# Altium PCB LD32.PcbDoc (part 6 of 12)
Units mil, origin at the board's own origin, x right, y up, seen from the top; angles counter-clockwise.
Board outline 7007.87 x 4368.85 mil, 12 copper layers (Top Layer, Int1 (GND), Int2 (AVDD), Int3 (DVDD), Int4 (GND), Int5 (ST), Int6 (SB), Int8 (AGND), Int7 (AVCC), Int9 (VCCA), Int10 (GND), Bottom Layer), stack 60.136 mil thick; 1165 components, 667 nets, 3910 pads, 2570 vias.
Unrouted connection lines stored in the file: 14.
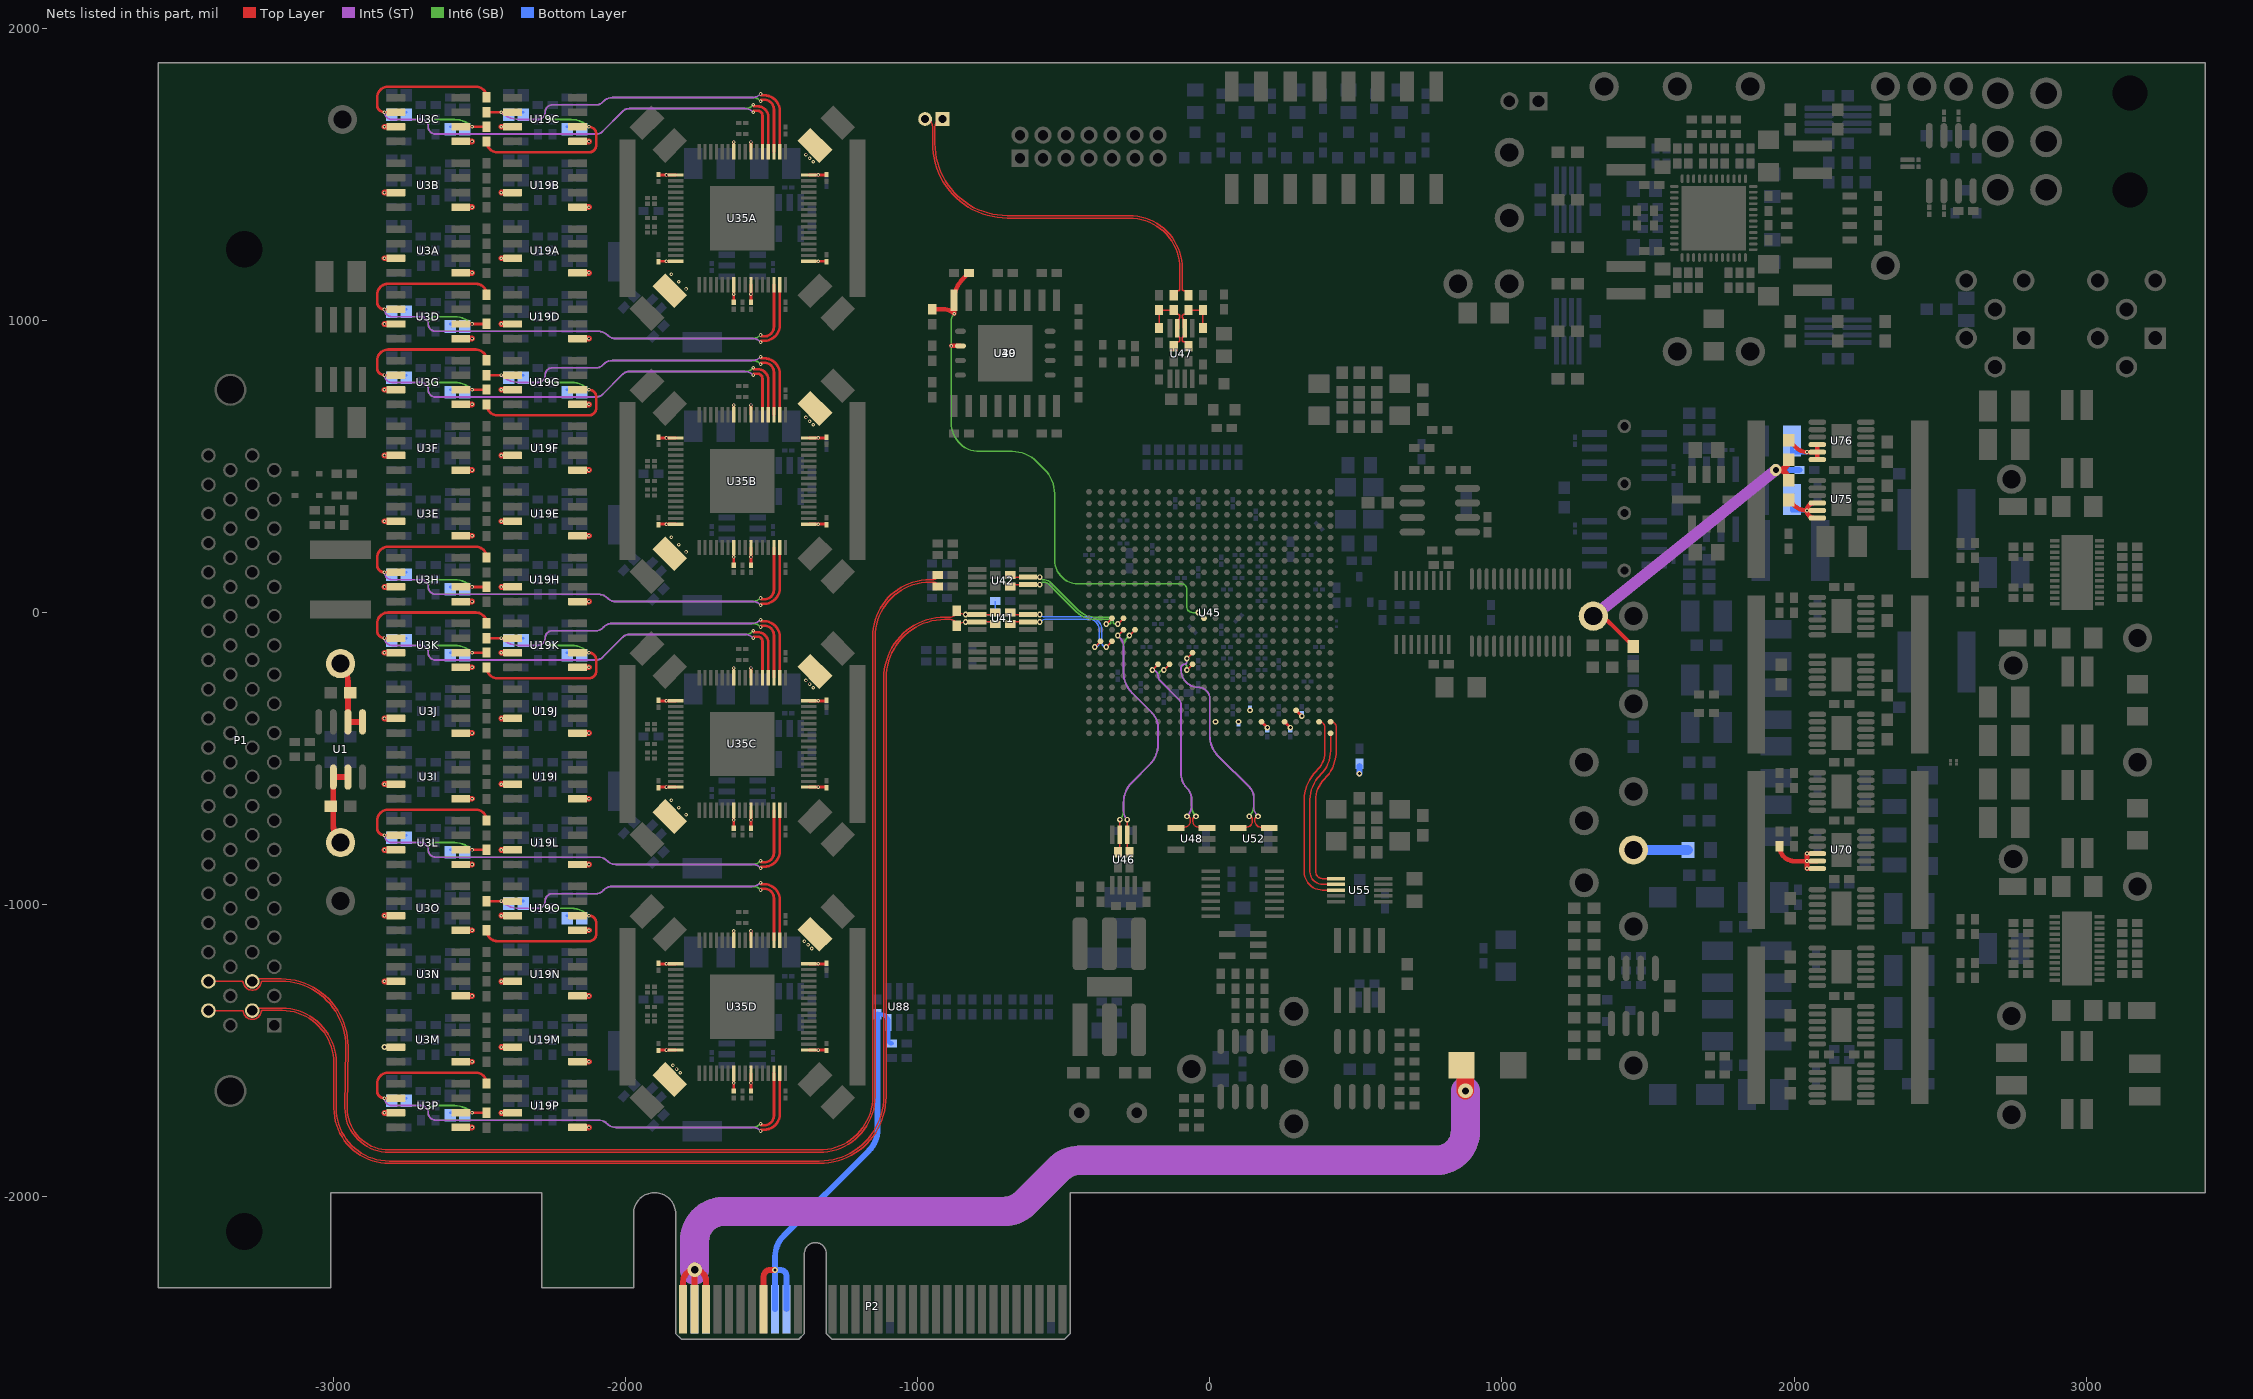
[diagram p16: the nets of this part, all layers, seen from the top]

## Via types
v1: diameter 12, hole 6, Top Layer to Bottom Layer, tented both sides, 1500 vias
v2: diameter 19, hole 10, Top Layer to Bottom Layer, tented both sides, 404 vias
v3: diameter 20, hole 10, Top Layer to Bottom Layer, tented both sides, 337 vias
v4: diameter 14, hole 7, Top Layer to Bottom Layer, tented both sides, 212 vias
v5: diameter 30, hole 15, Top Layer to Bottom Layer, tented both sides, 37 vias
v6: diameter 19.68, hole 7.87, Top Layer to Bottom Layer, 25 vias
v7: diameter 40, hole 20, Top Layer to Bottom Layer, tented both sides, 16 vias
v8: diameter 19.02, hole 10, Top Layer to Bottom Layer, tented both sides, 10 vias
v9: diameter 40, hole 20, Top Layer to Bottom Layer, 9 vias
v10: diameter 60, hole 40, Top Layer to Bottom Layer, 5 vias
v11: diameter 25, hole 13, Top Layer to Bottom Layer, 4 vias
v12: diameter 50, hole 25, Top Layer to Bottom Layer, tented both sides, 4 vias
v13: diameter 35, hole 20, Top Layer to Bottom Layer, 2 vias
v14: diameter 50, hole 25, Top Layer to Bottom Layer, 2 vias
v15: diameter 63, hole 45, Top Layer to Bottom Layer, 1 vias
v16: diameter 14.02, hole 7.01, Top Layer to Bottom Layer, tented both sides, 1 vias
v17: diameter 60, hole 40, Top Layer to Bottom Layer, tented both sides, 1 vias

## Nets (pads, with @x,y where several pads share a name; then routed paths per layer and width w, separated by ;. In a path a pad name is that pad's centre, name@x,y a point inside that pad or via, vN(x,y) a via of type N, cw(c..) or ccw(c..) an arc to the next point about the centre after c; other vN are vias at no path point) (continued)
AVCC3.3V: C7A.2 C7B.2 C7C.2 C7D.2 C19A.2 C19B.2 C19C.2 C19D.2 C20A.2 C20B.2 C20C.2 C20D.2 C27A.2 C27B.2 C27C.2 C27D.2 C31A.2 C31B.2 C31C.2 C31D.2 C44A.2 C44B.2 C44C.2 C44D.2 C51A.2 C51B.2 C51C.2 C51D.2 C52A.2 C52B.2 C52C.2 C52D.2 R138.1 R152.1 R272.1 R273.2 TP15.1 U35A.7 U35A.10 U35A.17 U35A.32 U35A.39 U35A.42 U35A.49 U35A.64 U35B.7 U35B.10 U35B.17 U35B.32 U35B.39 U35B.42 U35B.49 U35B.64 U35C.7 U35C.10 U35C.17 U35C.32 U35C.39 U35C.42 U35C.49 U35C.64 U35D.7 U35D.10 U35D.17 U35D.32 U35D.39 U35D.42 U35D.49 U35D.64 | length 2853.9
  Top Layer w10: C19D.2@-1887.5,-1499.44 cw(c-1885.7,-1499.44) -1885.7,-1497.64 -1869.73,-1497.64 v1(-1860,-1497.64) U35D.32@-1827.5,-1497.64 ; C20D.2@-1887.5,-1200.56 ccw(c-1885.7,-1200.56) -1885.7,-1202.36 -1869.73,-1202.36 v1(-1860,-1202.36) U35D.17@-1827.5,-1202.36 ; C19C.2@-1887.5,-599.44 cw(c-1885.7,-599.44) -1885.7,-597.64 -1869.73,-597.64 v1(-1860,-597.64) U35C.32@-1827.5,-597.64 ; C20C.2@-1887.5,-300.56 ccw(c-1885.7,-300.56) -1885.7,-302.36 -1869.73,-302.36 v1(-1860,-302.36) U35C.17@-1827.5,-302.36 ; C19B.2@-1887.5,300.56 cw(c-1885.7,300.56) -1885.7,302.36 -1869.73,302.36 v1(-1860,302.36) U35B.32@-1827.5,302.36 ; C20B.2@-1887.5,599.44 ccw(c-1885.7,599.44) -1885.7,597.64 -1869.73,597.64 v1(-1860,597.64) U35B.17@-1827.5,597.64 ; C19A.2@-1887.5,1200.56 cw(c-1885.7,1200.56) -1885.7,1202.36 -1869.73,1202.36 v1(-1860,1202.36) U35A.32@-1827.5,1202.36 ; C20A.2@-1887.5,1499.44 ccw(c-1885.7,1499.44) -1885.7,1497.64 -1869.73,1497.64 v1(-1860,1497.64) U35A.17@-1827.5,1497.64 ; C27D.2@-1629.53,-1632.5 v1(-1629.53,-1610) U35D.39@-1629.53,-1577.5 ; U35D.10@-1629.53,-1122.5 v1(-1629.53,-1090) ; C27C.2@-1629.53,-732.5 v1(-1629.53,-710) U35C.39@-1629.53,-677.5 ; U35C.10@-1629.53,-222.5 v1(-1629.53,-190) ; C27B.2@-1629.53,167.5 v1(-1629.53,190) U35B.39@-1629.53,222.5 ; U35B.10@-1629.53,677.5 v1(-1629.53,710) ; C27A.2@-1629.53,1067.5 v1(-1629.53,1090) U35A.39@-1629.53,1122.5 ; U35A.10@-1629.53,1577.5 v1(-1629.53,1610) ; C31D.2@-1570.47,-1632.5 v1(-1570.47,-1610) U35D.42@-1570.47,-1577.5 ; U35D.7@-1570.47,-1122.5 v1(-1570.47,-1090) ; C31C.2@-1570.47,-732.5 v1(-1570.47,-710) U35C.42@-1570.47,-677.5 ; U35C.7@-1570.47,-222.5 v1(-1570.47,-190) ; C31B.2@-1570.47,167.5 v1(-1570.47,190) U35B.42@-1570.47,222.5 ; U35B.7@-1570.47,677.5 v1(-1570.47,710) ; C31A.2@-1570.47,1067.5 v1(-1570.47,1090) U35A.42@-1570.47,1122.5 ; U35A.7@-1570.47,1577.5 v1(-1570.47,1610) ; U35D.49@-1372.5,-1497.64 v1(-1340,-1497.64) -1330.27,-1497.64 -1314.3,-1497.64 cw(c-1314.3,-1499.44) C51D.2@-1312.5,-1499.44 ; U35D.64@-1372.5,-1202.36 v1(-1340,-1202.36) -1330.27,-1202.36 -1314.3,-1202.36 ccw(c-1314.3,-1200.56) C52D.2@-1312.5,-1200.56 ; U35C.49@-1372.5,-597.64 v1(-1340,-597.64) -1330.27,-597.64 -1314.3,-597.64 cw(c-1314.3,-599.44) C51C.2@-1312.5,-599.44 ; U35C.64@-1372.5,-302.36 v1(-1340,-302.36) -1330.27,-302.36 -1314.3,-302.36 ccw(c-1314.3,-300.56) C52C.2@-1312.5,-300.56 ; U35B.49@-1372.5,302.36 v1(-1340,302.36) -1330.27,302.36 -1314.3,302.36 cw(c-1314.3,300.56) C51B.2@-1312.5,300.56 ; U35B.64@-1372.5,597.64 v1(-1340,597.64) -1330.27,597.64 -1314.3,597.64 ccw(c-1314.3,599.44) C52B.2@-1312.5,599.44 ; U35A.49@-1372.5,1202.36 v1(-1340,1202.36) -1330.27,1202.36 -1314.3,1202.36 cw(c-1314.3,1200.56) C51A.2@-1312.5,1200.56 ; U35A.64@-1372.5,1497.64 v1(-1340,1497.64) -1330.27,1497.64 -1314.3,1497.64 ccw(c-1314.3,1499.44) C52A.2@-1312.5,1499.44
  Top Layer w15: TP15.1@1312.5,-12.5 cw(c1312.5,-93.29) 1369.63,-36.16 R138.1@1450,-116.54
  Top Layer w20: v7(1937.5,487.5) v7@1945.96,487.5 ; R273.2@1981.25,452.21 ccw(c1945.96,452.21) v7@1945.96,487.5 ; R272.1@1981.25,522.79 cw(c1945.96,522.79) v7@1945.96,487.5
  Int5 (ST) w40: TP15.1@1312.5,-12.5 v7(1937.5,487.5)
  Bottom Layer w20: v7(1937.5,487.5) R152.1@2018.16,487.5
  other v1: -1812.5,-1575 -1825,-1562.5 -1837.5,-1550 -1362.5,-1150 -1375,-1137.5 -1387.5,-1125 -1792.5,-692.5 -1817.5,-667.5 -1842.5,-642.5 -1357.5,-257.5 -1370,-245 -1382.5,-232.5 -1792.5,207.5 -1817.5,232.5 -1842.5,257.5 -1357.5,642.5 -1370,655 -1382.5,667.5 -1792.5,1107.5 -1817.5,1132.5 -1842.5,1157.5 -1357.5,1542.5 -1370,1555 -1382.5,1567.5
AVCCL3.3V: C170.2 R273.1 U75.10 U75.11 U75.12 | length 290.4
  Top Layer w15: R273.1@1981.25,385.29 1998.8,367.73 ccw(c2043.75,412.68) v4(2043.75,349.11) ; U75.12@2069.34,323.52 cw(c2069.34,349.11) v4(2043.75,349.11) ; U75.11@2079.44,349.11 v4(2043.75,349.11) ; U75.10@2079.44,374.7 2069.34,374.7 ccw(c2069.34,349.11) v4(2043.75,349.11)
  Bottom Layer w15: C170.2@1992.62,387.5 1992.62,349.11 v4(2043.75,349.11)
AVCCR3.3V: C171.2 R272.2 U76.10 U76.11 U76.12 | length 253.4
  Top Layer w15: R272.2@1981.25,589.71 2006.37,564.6 ccw(c2043.75,601.98) v4(2043.75,549.11) U76.11@2079.44,549.11 ; U76.12@2079.44,523.52 U76.11@2079.44,549.11 ; U76.10@2079.44,574.7 U76.11@2079.44,549.11
  Bottom Layer w15: C171.2@1992.62,587.5 1992.62,549.11 v4(2043.75,549.11)
AVTT: C172.2 C210.1 C211.2 C216.1 C229.2 C238.2 R162.2 R287.2 TP19.1 U45.B5 U45.B7 U45.B9 U45.B11 U45.C4 U45.C8 U70.10 U70.11 U70.12 | length 576.4
  Top Layer w10: U45.B7@177.17,-374.02 v2(196.85,-393.7) ; U45.B5@255.91,-374.02 v2(275.59,-393.7) ; U45.C4@295.28,-334.65 v2(314.96,-354.33)
  Top Layer w16: R162.2@1950,-800.59 ccw(c2000.3,-800.59) 2000.3,-850.89 v4(2043.75,-850.89) ; U70.12@2079.44,-876.48 v4(2043.75,-876.48) v4(2043.75,-850.89) ; U70.11@2079.44,-850.89 v4(2043.75,-850.89) ; U70.10@2079.44,-825.3 v4(2043.75,-825.3) v4(2043.75,-850.89)
  Bottom Layer w20: v2(511.81,-551.18) R287.2@511.81,-525.59
  Bottom Layer w35: TP19.1@1450,-812.5 C172.2@1636.61,-812.5
  other v2: 19.69,-374.02 98.43,-374.02 137.8,-334.65
BUS3.3V: C286.1 P2.A9 P2.A10 P2.B8 R318.2 U88.6 | length 1606.9
  Top Layer w20: P2.B8@-1527.17,-2385 -1527.17,-2272.93 cw(c-1504.23,-2272.93) -1504.23,-2250 v3(-1487.8,-2250)
  Bottom Layer w15: C286.1@-1137.5,-1375.59 -1127.46,-1375.59 cw(c-1127.46,-1403.15) U88.6@-1099.9,-1403.15 -1099.9,-1463.19 ccw(c-1088.09,-1463.19) R318.2@-1088.09,-1475
  Bottom Layer w20: P2.A9@-1487.8,-2385 v3(-1487.8,-2250) ; P2.A10@-1448.43,-2385 -1448.43,-2272.77 ccw(c-1471.19,-2272.77) -1471.19,-2250 v3(-1487.8,-2250) ; C286.1@-1137.5,-1375.59 -1137.5,-1771.08 cw(c-1237.5,-1771.08) -1166.79,-1841.79 -1458.51,-2133.51 ccw(c-1387.8,-2204.22) -1487.8,-2204.22 v3(-1487.8,-2250)
BUS12V: D3.1 P2.A2 P2.A3 P2.B1 P2.B2 P2.B3 | length 6943.4
  Top Layer w20: P2.B1@-1802.76,-2385 -1802.76,-2289.37 cw(c-1763.39,-2289.37) v12(-1763.39,-2250) ; P2.B2@-1763.39,-2385 v12(-1763.39,-2250) ; P2.B3@-1724.02,-2385 -1724.02,-2289.37 ccw(c-1763.39,-2289.37) v12(-1763.39,-2250)
  Top Layer w60: D3.1@861.42,-1550 875,-1563.58 v12(875,-1637.5)
  Int5 (ST) w100: v12(-1763.39,-2250) -1763.39,-2150 cw(c-1663.39,-2150) -1663.39,-2050 -703.92,-2050 ccw(c-703.92,-1950) -633.21,-2020.71 -516.79,-1904.29 cw(c-446.08,-1975) -446.08,-1875 775,-1875 ccw(c775,-1775) 875,-1775 v12(875,-1637.5)
  Int6 (SB) w100: v12(-1763.39,-2250) -1763.39,-2150 cw(c-1663.39,-2150) -1663.39,-2050 -703.92,-2050 ccw(c-703.92,-1950) -633.21,-2020.71 -516.79,-1904.29 cw(c-446.08,-1975) -446.08,-1875 775,-1875 ccw(c775,-1775) 875,-1775 v12(875,-1637.5)
  Bottom Layer w20: P2.A2@-1763.39,-2385 v12(-1763.39,-2250) cw(c-1763.39,-2289.37) -1724.02,-2289.37 P2.A3@-1724.02,-2385
CAUX_N: C66.2 R99.2 R100.1 R101.1 U47.3 | length 262.8
  Top Layer w5: R99.2@-173.43,973.92 R100.1@-173.43,1035.24 C66.2@-123.43,1035.24 ccw(c-113.92,1035.24) -120.64,1028.52 -114.55,1022.42 ccw(c-108.75,1028.22) -108.75,1020.02 -107.43,1020.02 cw(c-107.43,1015.02) -103.89,1018.56 cw(c-107.43,1015.02) -102.43,1015.02 -102.43,1010.62 ccw(c-95.12,1003.31) -105.45,1003.31 -105.45,976.71 cw(c-125.14,976.71) -111.22,962.79 -111.22,959.56 ccw(c-86.71,959.56) -104.04,942.23 cw(c-107.95,938.33) -102.43,938.33 -102.43,931.63 cw(c-107.43,931.63) -103.89,928.1 cw(c-107.43,931.63) -107.43,926.63 -108.75,926.63 ccw(c-108.75,918.44) -114.55,924.23 -120.64,918.14 ccw(c-113.92,911.42) R101.1@-123.43,911.42
CAUX_P: C68.2 R104.1 R105.1 R106.2 U47.2 | length 262.8
  Top Layer w5: R104.1@-73.43,911.42 ccw(c-82.93,911.42) -76.21,918.14 -82.3,924.23 ccw(c-88.1,918.44) -88.1,926.63 -89.43,926.63 cw(c-89.43,931.63) -92.96,928.1 cw(c-89.43,931.63) -94.43,931.63 -94.43,938.33 cw(c-88.9,938.33) -92.81,942.23 ccw(c-110.14,959.56) -85.63,959.56 -85.63,966.1 cw(c-71.71,980.02) -91.4,980.02 -91.4,1003.31 ccw(c-101.73,1003.31) -94.43,1010.62 -94.43,1015.02 cw(c-89.43,1015.02) -92.96,1018.56 cw(c-89.43,1015.02) -89.43,1020.02 -88.1,1020.02 ccw(c-88.1,1028.22) -82.3,1022.42 -76.21,1028.52 ccw(c-82.93,1035.24) C68.2@-73.43,1035.24 R106.2@-23.43,1035.24 R105.1@-23.43,973.92
CCLK: R69.1 R73.2 U39.16 U40.6 U45.L12 | length 2006
  Top Layer w5: v2(-39.37,0) U45.L12@-19.68,-19.68
  Top Layer w15: R69.1@-950,1038.09 -912.64,1038.09 cw(c-912.64,984.86) v1(-875,1022.5) U39.16@-875,1068.6 -875,1070.49 cw(c-775,1070.49) -845.71,1141.2 R73.2@-824.41,1162.5 ; v1(-885,912.5) U40.6@-853.54,912.5
  Int6 (SB) w5: v1(-875,1022.5) ccw(c-850.86,998.36) -885,998.36 v1(-885,912.5) -885,648.78 ccw(c-787.4,648.78) -787.4,551.18 -676.55,551.18 cw(c-676.55,431.5) -591.92,516.13 -566.55,490.76 cw(c-651.18,406.13) -531.5,406.13 -531.5,179.92 ccw(c-450,179.92) -450,98.43 -98.43,98.43 ; -98.61,98.44 cw(c-98.61,78.57) -78.74,78.57 -78.74,19.69 ccw(c-59.06,19.69) -59.06,0 v2(-39.37,0)
CLK_AUX_N: C66.1 J1.2 | length 1311.8
  Top Layer w5: J1.2@-974.41,1688.98 cw(c-974.41,1663.45) -948.88,1663.45 -948.88,1605.97 ccw(c-693.18,1605.97) -693.18,1350.27 -275.67,1350.27 cw(c-275.67,1177.03) -102.43,1177.03 -102.43,1106.63 cw(c-107.43,1106.63) -103.89,1103.1 cw(c-107.42,1106.63) -107.42,1101.63 -108.75,1101.63 ccw(c-108.75,1093.44) -114.54,1099.24 -120.64,1093.14 ccw(c-113.92,1086.42) C66.1@-123.43,1086.42
  Bottom Layer w5: J1.2@-974.41,1688.98 J1.2@-959.67,1674.24
CLK_AUX_P: C68.1 J1.1 | length 1311.8
  Top Layer w5: J1.1@-915.35,1688.98 ccw(c-915.35,1663.45) -940.88,1663.45 -940.88,1605.97 ccw(c-693.18,1605.97) -693.18,1358.27 -275.67,1358.27 cw(c-275.67,1177.03) -94.43,1177.03 -94.43,1106.63 ccw(c-89.43,1106.63) -92.96,1103.1 ccw(c-89.43,1106.63) -89.43,1101.63 -88.1,1101.63 cw(c-88.1,1093.44) -82.3,1099.23 -76.21,1093.14 cw(c-82.93,1086.42) C68.1@-73.43,1086.42
  Bottom Layer w5: J1.1@-930.09,1674.24 J1.1@-915.35,1688.98
CLK_E_N: P1.4 R75.2 R78.1 R305.1 U41.3 | length 4888.8
  Top Layer w5: P1.4@-3427.3,-1362.5 -3312.42,-1362.5 cw(c-3312.45,-1367.5) -3307.5,-1366.78 ccw(c-3277.3,-1362.5) -3247.1,-1366.76 ccw(c-3277.3,-1362.5) -3247.02,-1366.15 cw(c-3242.06,-1366.77) -3242.16,-1361.77 ; -3242.11,-1361.77 -3175.4,-1361.77 cw(c-3178.08,-1541.71) -2998.12,-1541.71 -2998.12,-1696.24 ccw(c-2808.83,-1696.24) -2808.83,-1885.53 -1336.21,-1885.53 ccw(c-1336.21,-1657.21) -1107.89,-1657.21 -1107.89,-225.01 cw(c-906.56,-225.01) -906.56,-23.68 -887.73,-23.68 cw(c-887.73,-45.28) R75.2@-866.14,-45.28 -865.64,-44.77 cw(c-835.96,-74.45) v2(-835.96,-32.48) U41.3@-795.47,-32.48 -750.89,-32.48 cw(c-750.89,-56) R78.1@-734.25,-39.37
  Bottom Layer w5: v2(-835.96,-32.48) -750.89,-32.48 cw(c-750.89,-56) R305.1@-734.25,-39.37
CLK_E_P: P1.3 R75.1 R79.1 R306.1 R308.2 U41.2 | length 4751.4
  Top Layer w5: P1.3@-3277.3,-1362.5 cw(c-3268.57,-1362.5) -3268.57,-1353.77 -3175.35,-1353.77 cw(c-3178.08,-1541.71) -2990.12,-1541.71 -2990.12,-1696.24 ccw(c-2808.83,-1696.24) -2808.83,-1877.53 -1336.21,-1877.53 ccw(c-1336.21,-1657.21) -1115.89,-1657.21 -1115.89,-225.01 cw(c-906.56,-225.01) -906.56,-15.68 -887.73,-15.68 ccw(c-887.73,5.91) R75.1@-866.14,5.91 -865.64,5.4 ccw(c-835.96,35.08) v2(-835.96,-6.89) U41.2@-795.47,-6.89 -750.89,-6.89 ccw(c-750.89,16.63) R79.1@-734.25,0
  Bottom Layer w5: v2(-835.96,-6.89) -750.89,-6.89 ccw(c-750.89,16.63) R308.2@-734.25,0 R306.1@-734.25,39.37
CLK_O_N: C59.1 P1.8 | length 4754.6
  Top Layer w5: P1.8@-3427.3,-1262.5 -3312.42,-1262.5 cw(c-3312.45,-1267.5) -3307.5,-1266.78 ccw(c-3277.3,-1262.5) -3247.1,-1266.76 ccw(c-3277.3,-1262.5) -3247.02,-1266.14 cw(c-3242.06,-1266.76) -3242.14,-1261.76 ; -3242.1,-1261.76 -3178.38,-1261.76 cw(c-3180.7,-1484.86) -2957.59,-1485.26 -2957.6,-1486.43 -2960.53,-1695.65 ; -2960.54,-1695.69 -2960.54,-1695.8 ccw(c-2808.81,-1695.95) -2809.02,-1847.67 -1336.7,-1847.67 ccw(c-1336.7,-1656.72) -1145.75,-1656.72 -1145.75,-83.13 cw(c-958.35,-83.13) -958.35,104.27 -946.79,104.27 cw(c-946.79,88.58) C59.1@-931.1,88.58
CLK_O_P: C60.1 P1.7 | length 4577.7
  Top Layer w5: P1.7@-3277.3,-1262.5 cw(c-3268.56,-1262.5) -3268.56,-1253.76 -3178.29,-1253.76 cw(c-3180.7,-1484.86) -2949.59,-1485.3 -2949.6,-1486.43 cw(c-2957.6,-1486.43) -2949.6,-1486.5 ; -2949.6,-1486.54 -2952.54,-1695.77 -2952.54,-1695.86 ccw(c-2808.81,-1695.95) -2809.01,-1839.67 -1336.7,-1839.67 ccw(c-1336.7,-1656.72) -1153.75,-1656.72 -1153.75,-83.13 cw(c-958.35,-83.13) -958.35,112.27 -946.79,112.27 ccw(c-946.79,127.95) C60.1@-931.1,127.95
CLKE_N: R78.2 U41.6 U45.J21 | length 425.6
  Top Layer w5: R78.2@-683.07,-39.37 cw(c-666.44,-56) -666.44,-32.48 U41.6@-622.24,-32.48 v2(-582.07,-32.48) ; v2(-393.7,-118.11) U45.J21@-374.02,-98.43
  Bottom Layer w5: v2(-582.07,-32.48) cw(c-559.98,-54.57) -559.98,-23.33 -413.74,-23.33 cw(c-413.74,-59.06) -378.02,-59.06 -378.02,-102.43 cw(c-393.7,-102.43) v2(-393.7,-118.11)
CLKE_P: R79.2 U41.7 U45.J20 | length 438
  Top Layer w5: R79.2@-683.07,0 ccw(c-666.44,16.63) -666.44,-6.89 U41.7@-622.24,-6.89 v2(-582.07,-6.89) ; v2(-354.33,-118.11) U45.J20@-334.65,-98.43
  Bottom Layer w5: v2(-582.07,-6.89) ccw(c-561.69,13.49) -561.69,-15.33 -413.74,-15.33 cw(c-413.74,-59.06) -370.02,-59.06 -370.02,-102.43 ccw(c-354.33,-102.43) v2(-354.33,-118.11)
CLKO_N: R80.2 U42.6 U45.L20 | length 411.6
  Top Layer w5: R80.2@-683.07,88.58 cw(c-666.44,71.95) -666.44,95.47 U42.6@-622.24,95.47 ; v2(-354.33,-39.37) U45.L20@-334.65,-19.68
  Int6 (SB) w5: v2(-582.07,95.47) -574.97,102.57 cw(c-570.87,98.46) -570.87,104.27 cw(c-570.87,74.39) -549.73,95.52 -456.67,2.45 ccw(c-393.72,65.4) -393.72,-23.62 -344.55,-23.62 cw(c-344.55,-29.53) -338.64,-29.53 -338.64,-33.46 cw(c-344.55,-33.46) -344.55,-39.37 v2(-354.33,-39.37)
CLKO_P: R81.2 U42.7 U45.L19 | length 424.1
  Top Layer w5: R81.2@-683.07,127.95 ccw(c-666.44,144.59) -666.44,121.06 U42.7@-622.24,121.06 ; v2(-314.96,-39.37) U45.L19@-295.28,-19.68
  Int6 (SB) w5: v2(-582.07,121.06) -574.97,113.97 ccw(c-570.87,118.07) -570.87,112.26 cw(c-570.87,74.39) -544.08,101.17 -451.02,8.1 ccw(c-393.72,65.4) -393.72,-15.63 -344.55,-15.63 cw(c-344.55,-29.53) -330.65,-29.53 -330.65,-33.46 ccw(c-324.74,-33.46) -324.74,-39.37 v2(-314.96,-39.37)
CLOCK.ACLK: U45.B2 U55.8 | length 688.8
  Top Layer w5: U45.B2@374.02,-374.02 cw(c374.02,-393.7) 393.7,-393.7 393.7,-479.52 cw(c312.59,-479.52) 369.94,-536.88 363.95,-542.87 ccw(c462.5,-641.42) 323.13,-641.42 323.13,-887.5 ccw(c385.63,-887.5) 385.63,-950 U55.8@431.79,-950
CLOCK.ACNV: U45.B1 U55.6 | length 626.2
  Top Layer w5: U45.B1@413.39,-374.02 cw(c413.39,-393.7) 433.07,-393.7 433.07,-472.05 cw(c294.55,-472.05) 392.5,-570 391.79,-570.71 ccw(c462.5,-641.42) 362.5,-641.42 362.5,-887.5 ccw(c385.63,-887.5) 385.63,-910.63 U55.6@431.79,-910.63
CLOCK.AIN: U45.A1 U55.7 | length 606.5
  Top Layer w5: U45.A1@413.39,-413.39 413.39,-472.34 cw(c295.24,-472.34) 378.78,-555.88 377.87,-556.79 ccw(c462.5,-641.42) 342.82,-641.42 342.82,-887.5 ccw(c385.63,-887.5) 385.63,-930.31 U55.7@431.79,-930.31
CLOCK.CNTROUT_N: U45.G16 U48.4 | length 669.8
  Top Layer w5: v2(-196.85,-196.85) U45.G16@-177.17,-177.17 ; U48.4@-115.65,-737.6 cw(c-109.61,-743.63) -109.61,-735.1 -89.23,-735.1 ccw(c-89.23,-712.37) -66.5,-712.37 -66.5,-708.5 ccw(c-77.5,-708.5) v3(-77.5,-697.5)
  Int5 (ST) w6: v2(-196.85,-196.85) cw(c-196.85,-216.54) -177.17,-216.54 ; -177.17,-214.57 -177.17,-216.54 ; -105.38,-298.16 -170.21,-233.34 cw(c-153.41,-216.54) -177.17,-216.54 ; -105.38,-298.16 cw(c-122.19,-314.96) -98.43,-314.96 -98.43,-552.87 ccw(c-31.22,-552.87) -78.74,-600.39 cw(c-117.95,-639.6) -62.5,-639.6 -62.5,-661.29 cw(c-113.71,-661.29) v3(-77.5,-697.5)
CLOCK.CNTROUT_P: U45.G15 U48.3 | length 668
  Top Layer w5: v2(-157.48,-196.85) U45.G15@-137.8,-177.17 ; v3(-47.5,-697.5) ccw(c-47.5,-708.5) -58.5,-708.5 -58.5,-712.37 ccw(c-35.77,-712.37) -35.77,-735.1 -15.39,-735.1 cw(c-15.39,-743.63) U48.3@-9.35,-737.6
  Int6 (SB) w6: v2(-157.48,-196.85) ccw(c-157.48,-216.54) -177.17,-216.41 ; -105.38,-298.16 -170.21,-233.34 cw(c-153.41,-216.54) -177.17,-216.54 ; -105.38,-298.16 cw(c-122.19,-314.96) -98.43,-314.96 -98.43,-552.87 ccw(c-31.22,-552.87) -78.74,-600.39 cw(c-117.95,-639.6) -62.5,-639.6 -62.5,-661.29 ccw(c-11.29,-661.29) v3(-47.5,-697.5) ; -177.17,-216.54 cw(c-157.48,-216.54) -177.17,-216.41 ; -177.17,-216.54 -177.17,-216.41
CLOCK.OSCCLK_N: R95.2 U45.K19 U46.6 | length 862.6
  Top Layer w5: v2(-314.96,-78.74) U45.K19@-295.28,-59.06 ; v2(-282.48,-708.66) U46.6@-282.48,-760.04 -282.48,-804.23 ccw(c-258.96,-804.23) R95.2@-275.59,-820.87
  Int5 (ST) w6: v2(-314.96,-78.74) -309.19,-84.51 cw(c-342.8,-118.11) -295.28,-118.11 -295.28,-204.64 ccw(c-195.28,-204.64) -265.99,-275.35 -198.04,-343.29 cw(c-248.45,-393.7) -177.17,-393.7 -177.17,-450.7 cw(c-277.17,-450.7) -206.45,-521.42 -265.99,-580.95 ccw(c-195.28,-651.66) -295.28,-651.66 -295.28,-677.17 ; -295.28,-677.77 ccw(c-251.59,-677.77) v2(-282.48,-708.66)
CLOCK.OSCCLK_P: R93.1 U45.K18 U46.7 | length 863.2
  Top Layer w5: R93.1@-314.96,-820.87 ccw(c-331.59,-804.23) -308.07,-804.23 U46.7@-308.07,-760.04 v2(-308.07,-708.66) ; v2(-275.59,-78.74) U45.K18@-255.91,-59.06
  Int6 (SB) w6: v2(-308.07,-708.66) ccw(c-338.96,-677.77) -295.28,-677.77 -295.28,-651.66 cw(c-195.28,-651.66) -265.99,-580.95 -206.45,-521.42 ccw(c-277.17,-450.7) -177.17,-450.7 -177.17,-393.7 ccw(c-248.45,-393.7) -198.04,-343.29 -265.99,-275.35 cw(c-195.28,-204.64) -295.28,-204.64 -295.28,-118.11 cw(c-247.75,-118.11) -281.36,-84.5 v2(-275.59,-78.74)
CLOCK.SYNC_N: U45.G13 U52.4 | length 779.4
  Top Layer w5: v2(-78.74,-196.85) U45.G13@-59.05,-177.17 ; U52.4@96.85,-737.6 cw(c102.89,-743.63) 102.89,-735.1 123.27,-735.1 ccw(c123.27,-712.37) 146,-712.37 146,-708.5 ccw(c135,-708.5) v3(135,-697.5)
  Int6 (SB) w6: v2(-78.74,-196.85) -78.74,-185.04 ccw(c-86.61,-185.04) -86.61,-177.17 ccw(c-86.61,-188.98) -98.43,-188.98 -98.43,-196.85 ccw(c-39.37,-196.85) -39.37,-255.91 cw(c-39.37,-295.28) 0,-295.28 0,-421.18 ccw(c100,-421.18) 29.29,-491.89 137.8,-600.39 cw(c108.33,-629.86) 150,-629.86 150,-662.5 cw(c101.72,-662.5) 135.86,-696.64 v3(135,-697.5)
CLOCK.SYNC_P: U45.H13 U52.3 | length 779.4
  Top Layer w5: v2(-78.74,-157.48) U45.H13@-59.05,-137.8 ; v3(165,-697.5) ccw(c165,-708.5) 154,-708.5 154,-712.37 ccw(c176.73,-712.37) 176.73,-735.1 197.11,-735.1 cw(c197.11,-743.63) U52.3@203.15,-737.6
  Int5 (ST) w6: v2(-78.74,-157.48) -78.74,-169.29 cw(c-86.61,-169.29) -86.61,-177.17 ccw(c-86.61,-188.98) -98.43,-188.98 -98.43,-196.85 ccw(c-39.37,-196.85) -39.37,-255.91 cw(c-39.37,-295.28) 0,-295.28 0,-421.18 ccw(c100,-421.18) 29.29,-491.89 137.8,-600.39 cw(c108.33,-629.86) 150,-629.86 150,-662.5 ccw(c198.28,-662.5) 164.14,-696.64 v3(165,-697.5)
COM1&2: C6.1 TP3.1 U1.1 U1.2 U3A.3 U3A.5 U3B.3 U3B.5 U3C.3 U3C.5 U3D.3 U3D.5 U3E.3 U3E.5 U3F.3 U3F.5 U3G.3 U3G.5 U3H.3 U3H.5 U19A.3 U19A.5 U19B.3 U19B.5 U19C.3 U19C.5 U19D.3 U19D.5 U19E.3 U19E.5 U19F.3 U19F.5 U19G.3 U19G.5 U19H.3 U19H.5 | length 1496.9
  Top Layer w20: TP3.1@-2975,-175 cw(c-3035.36,-235.36) -2950,-235.36 U1.2@-2950,-374.26 U1.1@-2900,-374.26 ; v1(-2825,87.5) U3H.3@-2786.22,87.5 ; v1(-2825,312.5) U3E.3@-2786.22,312.5 ; v1(-2825,537.5) U3F.3@-2786.22,537.5 ; v1(-2825,762.5) U3G.3@-2786.22,762.5 ; v1(-2825,987.5) U3D.3@-2786.22,987.5 ; v1(-2825,1212.5) U3A.3@-2786.22,1212.5 ; v1(-2825,1437.5) U3B.3@-2786.22,1437.5 ; v1(-2825,1662.5) U3C.3@-2786.22,1662.5 ; U3H.5@-2563.78,37.5 v1(-2525,37.5) ; U3E.5@-2563.78,262.5 v1(-2525,262.5) ; U3F.5@-2563.78,487.5 v1(-2525,487.5) ; U3G.5@-2563.78,712.5 v1(-2525,712.5) ; U3D.5@-2563.78,937.5 v1(-2525,937.5) ; U3A.5@-2563.78,1162.5 v1(-2525,1162.5) ; U3B.5@-2563.78,1387.5 v1(-2525,1387.5) ; U3C.5@-2563.78,1612.5 v1(-2525,1612.5) ; v1(-2425,87.5) U19H.3@-2386.22,87.5 ; v1(-2425,312.5) U19E.3@-2386.22,312.5 ; v1(-2425,537.5) U19F.3@-2386.22,537.5 ; v1(-2425,762.5) U19G.3@-2386.22,762.5 ; v1(-2425,987.5) U19D.3@-2386.22,987.5 ; v1(-2425,1212.5) U19A.3@-2386.22,1212.5 ; v1(-2425,1437.5) U19B.3@-2386.22,1437.5 ; v1(-2425,1662.5) U19C.3@-2386.22,1662.5 ; U19H.5@-2163.78,37.5 v1(-2125,37.5) ; U19E.5@-2163.78,262.5 v1(-2125,262.5) ; U19F.5@-2163.78,487.5 v1(-2125,487.5) ; U19G.5@-2163.78,712.5 v1(-2125,712.5) ; U19D.5@-2163.78,937.5 v1(-2125,937.5) ; U19A.5@-2163.78,1162.5 v1(-2125,1162.5) ; U19B.5@-2163.78,1387.5 v1(-2125,1387.5) ; U19C.5@-2163.78,1612.5 v1(-2125,1612.5)
COM3&4: C4.1 TP2.1 U1.6 U1.7 U3I.3 U3I.5 U3J.3 U3J.5 U3K.3 U3K.5 U3L.3 U3L.5 U3M.3 U3M.5 U3N.3 U3N.5 U3O.3 U3O.5 U3P.3 U3P.5 U19I.3 U19I.5 U19J.3 U19J.5 U19K.3 U19K.5 U19L.3 U19L.5 U19M.3 U19M.5 U19N.3 U19N.5 U19O.3 U19O.5 U19P.3 U19P.5 | length 1483.1
  Top Layer w20: TP2.1@-2975,-787.5 cw(c-2914.64,-727.14) -3000,-727.14 U1.6@-3000,-563.24 U1.7@-2950,-563.24 ; v1(-2825,-1712.5) U3P.3@-2786.22,-1712.5 ; v1(-2825,-1262.5) U3N.3@-2786.22,-1262.5 ; v1(-2825,-1037.5) U3O.3@-2786.22,-1037.5 ; v1(-2825,-812.5) U3L.3@-2786.22,-812.5 ; v1(-2825,-587.5) U3I.3@-2786.22,-587.5 ; v1(-2825,-362.5) U3J.3@-2786.22,-362.5 ; v1(-2825,-137.5) U3K.3@-2786.22,-137.5 ; U3P.5@-2563.78,-1762.5 v1(-2525,-1762.5) ; U3M.5@-2563.78,-1537.5 v1(-2525,-1537.5) ; U3N.5@-2563.78,-1312.5 v1(-2525,-1312.5) ; U3O.5@-2563.78,-1087.5 v1(-2525,-1087.5) ; U3L.5@-2563.78,-862.5 v1(-2525,-862.5) ; U3I.5@-2563.78,-637.5 v1(-2525,-637.5) ; U3J.5@-2563.78,-412.5 v1(-2525,-412.5) ; U3K.5@-2563.78,-187.5 v1(-2525,-187.5) ; v1(-2425,-1712.5) U19P.3@-2386.22,-1712.5 ; v1(-2425,-1487.5) U19M.3@-2386.22,-1487.5 ; v1(-2425,-1262.5) U19N.3@-2386.22,-1262.5 ; v1(-2425,-1037.5) U19O.3@-2386.22,-1037.5 ; v1(-2425,-812.5) U19L.3@-2386.22,-812.5 ; v1(-2425,-587.5) U19I.3@-2386.22,-587.5 ; v1(-2425,-362.5) U19J.3@-2386.22,-362.5 ; v1(-2425,-137.5) U19K.3@-2386.22,-137.5 ; U19P.5@-2163.78,-1762.5 v1(-2125,-1762.5) ; U19M.5@-2163.78,-1537.5 v1(-2125,-1537.5) ; U19N.5@-2163.78,-1312.5 v1(-2125,-1312.5) ; U19O.5@-2163.78,-1087.5 v1(-2125,-1087.5) ; U19L.5@-2163.78,-862.5 v1(-2125,-862.5) ; U19I.5@-2163.78,-637.5 v1(-2125,-637.5) ; U19J.5@-2163.78,-412.5 v1(-2125,-412.5) ; U19K.5@-2163.78,-187.5 v1(-2125,-187.5)
  other v3: -2825,-1487.5
D1A_N: C319C.2 R7C.2 R335C.1 U19C.6 U35A.3 | length 2567.5
  Top Layer w9: U19C.6@-2163.78,1662.5 v1(-2125,1662.5) ; v1(-1537.5,1750) cw(c-1532.5,1750) -1532.5,1755 -1525,1755 cw(c-1525,1721.73) -1491.73,1721.73 U35A.3@-1491.73,1577.5 ; R7C.2@-2475,1611.91 ccw(c-2438.09,1611.91) -2438.09,1575 ; R7C.2@-2475,1611.91 ccw(c-2438.09,1611.91) -2438.09,1575 ; R7C.2@-2475,1611.91 ccw(c-2438.09,1611.91) -2438.09,1575 ; R7C.2@-2475,1611.91 ccw(c-2438.09,1611.91) -2438.09,1575 ; R7C.2@-2475,1611.91 ccw(c-2438.09,1611.91) -2438.09,1575 ; -2438.09,1575 -2125,1575 ; -2125,1575 ccw(c-2125,1600) -2100,1600 ; -2125,1575 ccw(c-2125,1600) -2100,1600 ; -2125,1575 ccw(c-2125,1600) -2100,1600 ; -2125,1575 ccw(c-2125,1600) -2100,1600 ; -2125,1575 ccw(c-2125,1600) -2100,1600 ; -2125,1575 ccw(c-2125,1600) -2100,1600 ; -2125,1575 ccw(c-2125,1600) -2100,1600 ; -2125,1575 ccw(c-2125,1600) -2100,1600 ; -2125,1575 ccw(c-2125,1600) -2100,1600 ; -2125,1575 ccw(c-2125,1600) -2100,1600 ; -2125,1575 ccw(c-2125,1600) -2100,1600 ; v1(-2125,1662.5) cw(c-2125,1637.5) -2100,1637.5 ; v1(-2125,1662.5) cw(c-2125,1637.5) -2100,1637.5 ; v1(-2125,1662.5) cw(c-2125,1637.5) -2100,1637.5 ; v1(-2125,1662.5) cw(c-2125,1637.5) -2100,1637.5 ; v1(-2125,1662.5) cw(c-2125,1637.5) -2100,1637.5 ; v1(-2125,1662.5) cw(c-2125,1637.5) -2100,1637.5 ; -2100,1600 -2100,1637.5
  Int6 (SB) w6: v1(-2125,1662.5) ccw(c-2185.36,1602.14) -2185.36,1687.5 -2250,1687.5 cw(c-2250,1712.5) -2275,1712.5 cw(c-2250,1712.5) -2250,1737.5 -2100,1737.5 ccw(c-2100,1767.68) -2078.66,1746.34 -2075,1750 cw(c-2044.82,1719.82) -2044.82,1762.5 -1562.5,1762.5 cw(c-1562.5,1732.32) -1541.16,1753.66 v1(-1537.5,1750)
  Bottom Layer w9: R335C.1@-2200,1662.5 v1(-2125,1662.5)
D1A_P: C383C.2 R8C.2 R383C.1 U19C.2 U35A.2 | length 1641.5
  Top Layer w9: R8C.2@-2475,1711.91 v1(-2425,1712.5) U19C.2@-2386.22,1712.5 U19C.2@-2380,1712.5 ; v1(-1537.5,1775) ccw(c-1532.5,1775) -1532.5,1770 -1525,1770 cw(c-1525,1717.05) -1472.05,1717.05 U35A.2@-1472.05,1577.5
  Int5 (ST) w6: v1(-2425,1712.5) ccw(c-2364.64,1772.86) -2364.64,1687.5 -2300,1687.5 ccw(c-2300,1712.5) -2275,1712.5 cw(c-2250,1712.5) -2250,1737.5 ; v1(-1537.5,1775) cw(c-1567.68,1805.18) -1567.5,1762.5 ; -2250,1737.5 -2100,1737.5 ; -2250,1737.5 -2100,1737.5 ; -2250,1737.5 -2100,1737.5 ; -2100,1737.5 ccw(c-2100,1767.68) -2078.66,1746.34 -2075,1750 cw(c-2044.82,1719.82) -2044.82,1762.5 -1567.68,1762.5 ; -1567.68,1762.5 ccw(c-1567.68,1805.18) -1567.5,1762.5 ; -1567.68,1762.5 -1567.5,1762.5
  Bottom Layer w9: v1(-2425,1712.5) R383C.1@-2350,1712.5
D1B_N: C319G.2 R7G.2 R335G.1 U19G.6 U35B.3 | length 3385.1
  Top Layer w9: U19G.6@-2163.78,762.5 v1(-2125,762.5) ; -2100,700.08 cw(c-2125.08,700.08) -2125.08,675 -2438.09,675 ; v1(-1537.5,850) cw(c-1532.5,850) -1532.5,855 -1525,855 cw(c-1525,821.73) -1491.73,821.73 U35B.3@-1491.73,677.5 ; R7G.2@-2475,711.91 ccw(c-2438.09,711.91) -2438.09,675 ; R7G.2@-2475,711.91 ccw(c-2438.09,711.91) -2438.09,675 ; R7G.2@-2475,711.91 ccw(c-2438.09,711.91) -2438.09,675 ; R7G.2@-2475,711.91 ccw(c-2438.09,711.91) -2438.09,675 ; R7G.2@-2475,711.91 ccw(c-2438.09,711.91) -2438.09,675 ; -2125,675 ccw(c-2125,700) -2100,700 ; -2125,675 ccw(c-2125,700) -2100,700 ; -2125,675 ccw(c-2125,700) -2100,700 ; -2125,675 ccw(c-2125,700) -2100,700 ; -2125,675 ccw(c-2125,700) -2100,700 ; -2125,675 ccw(c-2125,700) -2100,700 ; -2125,675 ccw(c-2125,700) -2100,700 ; -2125,675 ccw(c-2125,700) -2100,700 ; -2125,675 ccw(c-2125,700) -2100,700 ; -2125,675 ccw(c-2125,700) -2100,700 ; -2125,675 ccw(c-2125,700) -2100,700 ; -2125,675 ccw(c-2125,700) -2100,700 ; -2125,675 ccw(c-2125,700) -2100,700 ; -2125,675 ccw(c-2125,700) -2100,700 ; -2125,675 ccw(c-2125,700) -2100,700 ; -2125,675 ccw(c-2125,700) -2100,700 ; -2125,675 ccw(c-2125,700) -2100,700 ; -2125,675 ccw(c-2125,700) -2100,700 ; -2125,675 ccw(c-2125,700) -2100,700 ; -2125,675 ccw(c-2125,700) -2100,700 ; -2125,675 ccw(c-2125,700) -2100,700 ; v1(-2125,762.5) cw(c-2125,737.5) -2100,737.5 ; v1(-2125,762.5) cw(c-2125,737.5) -2100,737.5 ; v1(-2125,762.5) cw(c-2125,737.5) -2100,737.5 ; v1(-2125,762.5) cw(c-2125,737.5) -2100,737.5 ; v1(-2125,762.5) cw(c-2125,737.5) -2100,737.5 ; v1(-2125,762.5) cw(c-2125,737.5) -2100,737.5 ; v1(-2125,762.5) cw(c-2125,737.5) -2100,737.5 ; v1(-2125,762.5) cw(c-2125,737.5) -2100,737.5 ; v1(-2125,762.5) cw(c-2125,737.5) -2100,737.5 ; v1(-2125,762.5) cw(c-2125,737.5) -2100,737.5 ; v1(-2125,762.5) cw(c-2125,737.5) -2100,737.5 ; v1(-2125,762.5) cw(c-2125,737.5) -2100,737.5 ; -2100,700 -2100,737.5
  Int6 (SB) w6: v1(-2125,762.5) ccw(c-2185.36,702.14) -2185.36,787.5 -2250,787.5 cw(c-2250,812.5) -2275,812.5 cw(c-2250,812.5) -2250,837.5 ; v1(-1537.5,850) -1541.16,853.66 ccw(c-1562.5,832.32) -1562.5,862.5 -2044.82,862.5 ccw(c-2044.82,819.82) -2075,850 -2078.66,846.34 cw(c-2100,867.68) -2100,837.5 ; -2250,837.5 -2100,837.5 ; -2250,837.5 -2100,837.5
  Bottom Layer w9: R335G.1@-2200,762.5 v1(-2125,762.5)
D1B_P: C383G.2 R8G.2 R383G.1 U19G.2 U35B.2 | length 2091.5
  Top Layer w9: R8G.2@-2475,811.91 v1(-2425,812.5) U19G.2@-2386.22,812.5 U19G.2@-2380,812.5 ; v1(-1537.5,875) ccw(c-1532.5,875) -1532.5,870 -1525,870 cw(c-1525,817.05) -1472.05,817.05 U35B.2@-1472.05,677.5
  Int5 (ST) w6: v1(-2425,812.5) ccw(c-2364.64,872.86) -2364.64,787.5 -2300,787.5 ccw(c-2300,812.5) -2275,812.5 cw(c-2250,812.5) -2250,837.5 ; v1(-1537.5,875) cw(c-1567.68,905.18) -1567.5,862.5 ; -2250,837.5 -2100,837.5 ; -2250,837.5 -2100,837.5 ; -2250,837.5 -2100,837.5 ; -2250,837.5 -2100,837.5 ; -2250,837.5 -2100,837.5 ; -2250,837.5 -2100,837.5 ; -2100,837.5 ccw(c-2100,867.68) -2078.66,846.34 -2075,850 cw(c-2044.82,819.82) -2044.82,862.5 -1567.68,862.5 ; -1567.68,862.5 ccw(c-1567.68,905.18) -1567.5,862.5 ; -1567.68,862.5 -1567.5,862.5
  Bottom Layer w9: v1(-2425,812.5) R383G.1@-2350,812.5
D1C_N: C319K.2 R7K.2 R335K.1 U19K.6 U35C.3 | length 3385.1
  Top Layer w9: U19K.6@-2163.78,-137.5 v1(-2125,-137.5) ; v1(-1537.5,-50) cw(c-1532.5,-50) -1532.5,-45 -1525,-45 cw(c-1525,-78.27) -1491.73,-78.27 U35C.3@-1491.73,-222.5 ; R7K.2@-2475,-188.09 ccw(c-2438.09,-188.09) -2438.09,-225 ; R7K.2@-2475,-188.09 ccw(c-2438.09,-188.09) -2438.09,-225 ; R7K.2@-2475,-188.09 ccw(c-2438.09,-188.09) -2438.09,-225 ; R7K.2@-2475,-188.09 ccw(c-2438.09,-188.09) -2438.09,-225 ; R7K.2@-2475,-188.09 ccw(c-2438.09,-188.09) -2438.09,-225 ; -2438.09,-225 -2125,-225 ; -2125,-225 ccw(c-2125,-200) -2100,-200 ; -2125,-225 ccw(c-2125,-200) -2100,-200 ; -2125,-225 ccw(c-2125,-200) -2100,-200 ; -2125,-225 ccw(c-2125,-200) -2100,-200 ; -2125,-225 ccw(c-2125,-200) -2100,-200 ; -2125,-225 ccw(c-2125,-200) -2100,-200 ; -2125,-225 ccw(c-2125,-200) -2100,-200 ; -2125,-225 ccw(c-2125,-200) -2100,-200 ; -2125,-225 ccw(c-2125,-200) -2100,-200 ; -2125,-225 ccw(c-2125,-200) -2100,-200 ; -2125,-225 ccw(c-2125,-200) -2100,-200 ; -2125,-225 ccw(c-2125,-200) -2100,-200 ; -2125,-225 ccw(c-2125,-200) -2100,-200 ; -2125,-225 ccw(c-2125,-200) -2100,-200 ; -2125,-225 ccw(c-2125,-200) -2100,-200 ; -2125,-225 ccw(c-2125,-200) -2100,-200 ; -2125,-225 ccw(c-2125,-200) -2100,-200 ; -2125,-225 ccw(c-2125,-200) -2100,-200 ; -2125,-225 ccw(c-2125,-200) -2100,-200 ; -2125,-225 ccw(c-2125,-200) -2100,-200 ; -2125,-225 ccw(c-2125,-200) -2100,-200 ; -2125,-225 ccw(c-2125,-200) -2100,-200 ; v1(-2125,-137.5) cw(c-2125,-162.5) -2100,-162.5 ; v1(-2125,-137.5) cw(c-2125,-162.5) -2100,-162.5 ; v1(-2125,-137.5) cw(c-2125,-162.5) -2100,-162.5 ; v1(-2125,-137.5) cw(c-2125,-162.5) -2100,-162.5 ; v1(-2125,-137.5) cw(c-2125,-162.5) -2100,-162.5 ; v1(-2125,-137.5) cw(c-2125,-162.5) -2100,-162.5 ; v1(-2125,-137.5) cw(c-2125,-162.5) -2100,-162.5 ; v1(-2125,-137.5) cw(c-2125,-162.5) -2100,-162.5 ; v1(-2125,-137.5) cw(c-2125,-162.5) -2100,-162.5 ; v1(-2125,-137.5) cw(c-2125,-162.5) -2100,-162.5 ; v1(-2125,-137.5) cw(c-2125,-162.5) -2100,-162.5 ; v1(-2125,-137.5) cw(c-2125,-162.5) -2100,-162.5 ; -2100,-200 -2100,-162.5
  Int6 (SB) w6: v1(-2125,-137.5) ccw(c-2185.36,-197.86) -2185.36,-112.5 -2250,-112.5 cw(c-2250,-87.5) -2275,-87.5 cw(c-2250,-87.5) -2250,-62.5 ; v1(-1537.5,-50) -1541.16,-46.34 ccw(c-1562.5,-67.68) -1562.5,-37.5 -2044.82,-37.5 ccw(c-2044.82,-80.18) -2075,-50 -2078.66,-53.66 cw(c-2100,-32.32) -2100,-62.5 ; -2250,-62.5 -2100,-62.5 ; -2250,-62.5 -2100,-62.5
  Bottom Layer w9: R335K.1@-2200,-137.5 v1(-2125,-137.5)
D1C_P: C383K.2 R8K.2 R383K.1 U19K.2 U35C.2 | length 2241.5
  Top Layer w9: R8K.2@-2475,-88.09 v1(-2425,-87.5) U19K.2@-2386.22,-87.5 U19K.2@-2380,-87.5 ; v1(-1537.5,-25) ccw(c-1532.5,-25) -1532.5,-30 -1525,-30 cw(c-1525,-82.95) -1472.05,-82.95 U35C.2@-1472.05,-222.5
  Int5 (ST) w6: v1(-2425,-87.5) ccw(c-2364.64,-27.14) -2364.64,-112.5 -2300,-112.5 ccw(c-2300,-87.5) -2275,-87.5 cw(c-2250,-87.5) -2250,-62.5 ; v1(-1537.5,-25) cw(c-1567.68,5.18) -1567.5,-37.5 ; -2250,-62.5 -2100,-62.5 ; -2250,-62.5 -2100,-62.5 ; -2250,-62.5 -2100,-62.5 ; -2250,-62.5 -2100,-62.5 ; -2250,-62.5 -2100,-62.5 ; -2250,-62.5 -2100,-62.5 ; -2250,-62.5 -2100,-62.5 ; -2100,-62.5 ccw(c-2100,-32.32) -2078.66,-53.66 -2075,-50 cw(c-2044.82,-80.18) -2044.82,-37.5 -1567.68,-37.5 ; -1567.68,-37.5 ccw(c-1567.68,5.18) -1567.5,-37.5 ; -1567.68,-37.5 -1567.5,-37.5
  Bottom Layer w9: v1(-2425,-87.5) R383K.1@-2350,-87.5
D1D_N: C319O.2 R7O.2 R335O.1 U19O.6 U35D.3 | length 2796
  Top Layer w9: U19O.6@-2163.78,-1037.5 v1(-2125,-1037.5) ; v1(-1537.5,-950) cw(c-1532.5,-950) -1532.5,-945 -1525,-945 cw(c-1525,-978.27) -1491.73,-978.27 U35D.3@-1491.73,-1122.5 ; R7O.2@-2475,-1088.09 ccw(c-2438.09,-1088.09) -2438.09,-1125 ; R7O.2@-2475,-1088.09 ccw(c-2438.09,-1088.09) -2438.09,-1125 ; R7O.2@-2475,-1088.09 ccw(c-2438.09,-1088.09) -2438.09,-1125 ; R7O.2@-2475,-1088.09 ccw(c-2438.09,-1088.09) -2438.09,-1125 ; R7O.2@-2475,-1088.09 ccw(c-2438.09,-1088.09) -2438.09,-1125 ; -2438.09,-1125 -2125,-1125 ; -2125,-1125 ccw(c-2125,-1100) -2100,-1100 ; -2125,-1125 ccw(c-2125,-1100) -2100,-1100 ; -2125,-1125 ccw(c-2125,-1100) -2100,-1100 ; -2125,-1125 ccw(c-2125,-1100) -2100,-1100 ; -2125,-1125 ccw(c-2125,-1100) -2100,-1100 ; -2125,-1125 ccw(c-2125,-1100) -2100,-1100 ; -2125,-1125 ccw(c-2125,-1100) -2100,-1100 ; -2125,-1125 ccw(c-2125,-1100) -2100,-1100 ; -2125,-1125 ccw(c-2125,-1100) -2100,-1100 ; -2125,-1125 ccw(c-2125,-1100) -2100,-1100 ; -2125,-1125 ccw(c-2125,-1100) -2100,-1100 ; -2125,-1125 ccw(c-2125,-1100) -2100,-1100 ; v1(-2125,-1037.5) cw(c-2125,-1062.5) -2100,-1062.5 ; v1(-2125,-1037.5) cw(c-2125,-1062.5) -2100,-1062.5 ; v1(-2125,-1037.5) cw(c-2125,-1062.5) -2100,-1062.5 ; v1(-2125,-1037.5) cw(c-2125,-1062.5) -2100,-1062.5 ; v1(-2125,-1037.5) cw(c-2125,-1062.5) -2100,-1062.5 ; v1(-2125,-1037.5) cw(c-2125,-1062.5) -2100,-1062.5 ; v1(-2125,-1037.5) cw(c-2125,-1062.5) -2100,-1062.5 ; -2100,-1100 -2100,-1062.5
  Int6 (SB) w6: v1(-2125,-1037.5) ccw(c-2185.36,-1097.86) -2185.36,-1012.5 -2250,-1012.5 cw(c-2250,-987.5) -2275,-987.5 cw(c-2250,-987.5) -2250,-962.5 ; v1(-1537.5,-950) -1541.16,-946.34 ccw(c-1562.5,-967.68) -1562.5,-937.5 -2044.82,-937.5 ccw(c-2044.82,-980.18) -2075,-950 -2078.66,-953.66 cw(c-2100,-932.32) -2100,-962.5 ; -2250,-962.5 -2100,-962.5 ; -2250,-962.5 -2100,-962.5
  Bottom Layer w9: R335O.1@-2200,-1037.5 v1(-2125,-1037.5)
D1D_P: C383O.2 R8O.2 R383O.1 U19O.2 U35D.2 | length 1641.5
  Top Layer w9: R8O.2@-2475,-988.09 v1(-2425,-987.5) U19O.2@-2386.22,-987.5 U19O.2@-2380,-987.5 ; v1(-1537.5,-925) ccw(c-1532.5,-925) -1532.5,-930 -1525,-930 cw(c-1525,-982.95) -1472.05,-982.95 U35D.2@-1472.05,-1122.5
  Int5 (ST) w6: v1(-2425,-987.5) ccw(c-2364.64,-927.14) -2364.64,-1012.5 -2300,-1012.5 ccw(c-2300,-987.5) -2275,-987.5 cw(c-2250,-987.5) -2250,-962.5 ; v1(-1537.5,-925) cw(c-1567.68,-894.82) -1567.5,-937.5 ; -2250,-962.5 -2100,-962.5 ; -2250,-962.5 -2100,-962.5 ; -2250,-962.5 -2100,-962.5 ; -2100,-962.5 ccw(c-2100,-932.32) -2078.66,-953.66 -2075,-950 cw(c-2044.82,-980.18) -2044.82,-937.5 -1567.68,-937.5 ; -1567.68,-937.5 ccw(c-1567.68,-894.82) -1567.5,-937.5 ; -1567.68,-937.5 -1567.5,-937.5
  Bottom Layer w9: v1(-2425,-987.5) R383O.1@-2350,-987.5
D2A_N: C399D.2 R7D.1 R399D.1 U3D.6 U35A.46 | length 2266.1
  Top Layer w9: U3D.6@-2563.78,987.5 v1(-2525,987.5) -2475.59,987.5 R7D.1@-2475,988.09 ; v1(-1537.5,950) ccw(c-1532.5,950) -1532.5,945 -1525,945 ccw(c-1525,978.27) -1491.73,978.27 U35A.46@-1491.73,1122.5
  Int6 (SB) w6: v1(-2525,987.5) ccw(c-2585.36,927.14) -2585.36,1012.5 -2650,1012.5 ccw(c-2650,987.5) -2650,962.5 ; v1(-1537.5,950) cw(c-1567.68,980.18) -1567.5,937.5 ; -2650,962.5 -2092.68,962.5 ; -2650,962.5 -2092.68,962.5 ; -2092.68,962.5 cw(c-2092.68,919.82) -2062.5,950 ccw(c-2032.32,980.18) -2032.32,937.5 -1567.68,937.5 ; -1567.68,937.5 ccw(c-1567.68,980.18) -1567.5,937.5 ; -1567.68,937.5 -1567.5,937.5
  Bottom Layer w9: R399D.1@-2600,987.5 v1(-2525,987.5)
D2A_P: C463D.2 R8D.1 R447D.1 U3D.2 U35A.47 | length 2406.4
  Top Layer w9: U3D.2@-2786.22,1037.5 v1(-2825,1037.5) cw(c-2825,1062.5) -2850,1062.5 -2850,1087.5 cw(c-2812.5,1087.5) -2812.5,1125 -2511.91,1125 ; v1(-1537.5,925) cw(c-1532.5,925) -1532.5,930 -1525,930 ccw(c-1525,982.95) -1472.05,982.95 U35A.47@-1472.05,1122.5 ; -2511.91,1125 cw(c-2511.91,1088.09) R8D.1@-2475,1088.09 ; -2511.91,1125 cw(c-2511.91,1088.09) R8D.1@-2475,1088.09 ; -2511.91,1125 cw(c-2511.91,1088.09) R8D.1@-2475,1088.09 ; -2511.91,1125 cw(c-2511.91,1088.09) R8D.1@-2475,1088.09 ; -2511.91,1125 cw(c-2511.91,1088.09) R8D.1@-2475,1088.09
  Int5 (ST) w6: v1(-2825,1037.5) ccw(c-2800,1037.5) -2800,1012.5 -2700,1012.5 cw(c-2700,987.5) -2675,987.5 ccw(c-2650,987.5) -2650,962.5 -2092.68,962.5 cw(c-2092.68,919.82) -2062.5,950 ccw(c-2032.32,980.18) -2032.32,937.5 -1562.5,937.5 cw(c-1562.5,907.32) -1541.16,928.66 v1(-1537.5,925)
  Bottom Layer w9: v1(-2825,1037.5) R447D.1@-2750,1037.5
D2B_N: C399H.2 R7H.1 R399H.1 U3H.6 U35B.46 | length 3380.8
  Top Layer w9: U3H.6@-2563.78,87.5 v1(-2525,87.5) -2475.59,87.5 R7H.1@-2475,88.09 ; v1(-1537.5,50) ccw(c-1532.5,50) -1532.5,45 -1525,45 ccw(c-1525,78.27) -1491.73,78.27 U35B.46@-1491.73,222.5
  Int6 (SB) w6: v1(-2525,87.5) ccw(c-2585.36,27.14) -2585.36,112.5 -2650,112.5 ccw(c-2650,87.5) -2650,62.5 ; v1(-1537.5,50) cw(c-1567.68,80.18) -1567.5,37.5 ; -2650,62.5 -2092.68,62.5 ; -2650,62.5 -2092.68,62.5 ; -2650,62.5 -2092.68,62.5 ; -2650,62.5 -2092.68,62.5 ; -2092.68,62.5 cw(c-2092.68,19.82) -2062.5,50 ccw(c-2032.32,80.18) -2032.32,37.5 -1567.68,37.5 ; -1567.68,37.5 ccw(c-1567.68,80.18) -1567.5,37.5 ; -1567.68,37.5 -1567.5,37.5
  Bottom Layer w9: R399H.1@-2600,87.5 v1(-2525,87.5)
D2B_P: C463H.2 R8H.1 R447H.1 U3H.2 U35B.47 | length 2963.7
  Top Layer w9: U3H.2@-2786.22,137.5 v1(-2825,137.5) cw(c-2825,162.5) -2850,162.5 -2850,187.5 cw(c-2812.5,187.5) -2812.5,225 -2511.91,225 ; v1(-1537.5,25) cw(c-1532.5,25) -1532.5,30 -1525,30 ccw(c-1525,82.95) -1472.05,82.95 U35B.47@-1472.05,222.5 ; -2511.91,225 cw(c-2511.91,188.09) R8H.1@-2475,188.09 ; -2511.91,225 cw(c-2511.91,188.09) R8H.1@-2475,188.09 ; -2511.91,225 cw(c-2511.91,188.09) R8H.1@-2475,188.09 ; -2511.91,225 cw(c-2511.91,188.09) R8H.1@-2475,188.09 ; -2511.91,225 cw(c-2511.91,188.09) R8H.1@-2475,188.09
  Int5 (ST) w6: v1(-2825,137.5) ccw(c-2800,137.5) -2800,112.5 -2700,112.5 cw(c-2700,87.5) -2675,87.5 ccw(c-2650,87.5) -2650,62.5 ; v1(-1537.5,25) -1541.16,28.66 ccw(c-1562.5,7.32) -1562.5,37.5 -2032.32,37.5 cw(c-2032.32,80.18) -2062.5,50 ccw(c-2092.68,19.82) -2092.68,62.5 ; -2650,62.5 -2092.68,62.5 ; -2650,62.5 -2092.68,62.5
  Bottom Layer w9: v1(-2825,137.5) R447H.1@-2750,137.5
D2C_N: C399L.2 R7L.1 R399L.1 U3L.6 U35C.46 | length 3380.8
  Top Layer w9: U3L.6@-2563.78,-812.5 v1(-2525,-812.5) -2475.59,-812.5 R7L.1@-2475,-811.91 ; v1(-1537.5,-850) ccw(c-1532.5,-850) -1532.5,-855 -1525,-855 ccw(c-1525,-821.73) -1491.73,-821.73 U35C.46@-1491.73,-677.5
  Int6 (SB) w6: v1(-2525,-812.5) ccw(c-2585.36,-872.86) -2585.36,-787.5 -2650,-787.5 ccw(c-2650,-812.5) -2650,-837.5 ; v1(-1537.5,-850) cw(c-1567.68,-819.82) -1567.5,-862.5 ; -2650,-837.5 -2092.68,-837.5 ; -2650,-837.5 -2092.68,-837.5 ; -2650,-837.5 -2092.68,-837.5 ; -2650,-837.5 -2092.68,-837.5 ; -2092.68,-837.5 cw(c-2092.68,-880.18) -2062.5,-850 ccw(c-2032.32,-819.82) -2032.32,-862.5 -1567.68,-862.5 ; -1567.68,-862.5 ccw(c-1567.68,-819.82) -1567.5,-862.5 ; -1567.68,-862.5 -1567.5,-862.5
  Bottom Layer w9: R399L.1@-2600,-812.5 v1(-2525,-812.5)
D2C_P: C463L.2 R8L.1 R447L.1 U3L.2 U35C.47 | length 2964.8
  Top Layer w9: -2813.53,-674.92 -2511.91,-674.92 -2511.91,-675 ; -2812.5,-675 ccw(c-2812.5,-712.5) -2850,-712.5 -2850,-737.5 ccw(c-2825,-737.5) v1(-2825,-762.5) U3L.2@-2786.22,-762.5 ; v1(-1537.5,-875) cw(c-1532.5,-875) -1532.5,-870 -1525,-870 ccw(c-1525,-817.05) -1472.05,-817.05 U35C.47@-1472.05,-677.5 ; -2511.91,-675 cw(c-2511.91,-711.91) R8L.1@-2475,-711.91 ; -2511.91,-675 cw(c-2511.91,-711.91) R8L.1@-2475,-711.91 ; -2511.91,-675 cw(c-2511.91,-711.91) R8L.1@-2475,-711.91 ; -2511.91,-675 cw(c-2511.91,-711.91) R8L.1@-2475,-711.91 ; -2511.91,-675 cw(c-2511.91,-711.91) R8L.1@-2475,-711.91
  Int5 (ST) w6: v1(-2825,-762.5) ccw(c-2800,-762.5) -2800,-787.5 -2700,-787.5 cw(c-2700,-812.5) -2675,-812.5 ccw(c-2650,-812.5) -2650,-837.5 ; v1(-1537.5,-875) -1541.16,-871.34 ccw(c-1562.5,-892.68) -1562.5,-862.5 -2032.32,-862.5 cw(c-2032.32,-819.82) -2062.5,-850 ccw(c-2092.68,-880.18) -2092.68,-837.5 ; -2650,-837.5 -2092.68,-837.5 ; -2650,-837.5 -2092.68,-837.5
  Bottom Layer w9: v1(-2825,-762.5) R447L.1@-2750,-762.5
D2D_N: C399P.2 R7P.1 R399P.1 U3P.6 U35D.46 | length 2823.4
  Top Layer w9: U3P.6@-2563.78,-1712.5 v1(-2525,-1712.5) -2475.59,-1712.5 R7P.1@-2475,-1711.91 ; v1(-1537.5,-1750) ccw(c-1532.5,-1750) -1532.5,-1755 -1525,-1755 ccw(c-1525,-1721.73) -1491.73,-1721.73 U35D.46@-1491.73,-1577.5
  Int6 (SB) w6: v1(-2525,-1712.5) ccw(c-2585.36,-1772.86) -2585.36,-1687.5 -2650,-1687.5 ccw(c-2650,-1712.5) -2675,-1712.5 ccw(c-2650,-1712.5) -2650,-1737.5 ; v1(-1537.5,-1750) cw(c-1567.68,-1719.82) -1567.5,-1762.5 ; -2650,-1737.5 -2092.68,-1737.5 ; -2650,-1737.5 -2092.68,-1737.5 ; -2650,-1737.5 -2092.68,-1737.5 ; -2092.68,-1737.5 cw(c-2092.68,-1780.18) -2062.5,-1750 ccw(c-2032.32,-1719.82) -2032.32,-1762.5 -1567.68,-1762.5 ; -1567.68,-1762.5 ccw(c-1567.68,-1719.82) -1567.5,-1762.5 ; -1567.68,-1762.5 -1567.5,-1762.5
  Bottom Layer w9: R399P.1@-2600,-1712.5 v1(-2525,-1712.5)
D2D_P: C463P.2 R8P.1 R447P.1 U3P.2 U35D.47 | length 2406.4
  Top Layer w9: U3P.2@-2786.22,-1662.5 v1(-2825,-1662.5) cw(c-2825,-1637.5) -2850,-1637.5 -2850,-1612.5 cw(c-2812.5,-1612.5) -2812.5,-1575 -2511.91,-1575 ; v1(-1537.5,-1775) cw(c-1532.5,-1775) -1532.5,-1770 -1525,-1770 ccw(c-1525,-1717.05) -1472.05,-1717.05 U35D.47@-1472.05,-1577.5 ; -2511.91,-1575 cw(c-2511.91,-1611.91) R8P.1@-2475,-1611.91 ; -2511.91,-1575 cw(c-2511.91,-1611.91) R8P.1@-2475,-1611.91 ; -2511.91,-1575 cw(c-2511.91,-1611.91) R8P.1@-2475,-1611.91 ; -2511.91,-1575 cw(c-2511.91,-1611.91) R8P.1@-2475,-1611.91 ; -2511.91,-1575 cw(c-2511.91,-1611.91) R8P.1@-2475,-1611.91
  Int5 (ST) w6: v1(-2825,-1662.5) ccw(c-2800,-1662.5) -2800,-1687.5 -2700,-1687.5 cw(c-2700,-1712.5) -2675,-1712.5 ccw(c-2650,-1712.5) -2650,-1737.5 -2092.68,-1737.5 cw(c-2092.68,-1780.18) -2062.5,-1750 ccw(c-2032.32,-1719.82) -2032.32,-1762.5 -1562.5,-1762.5 cw(c-1562.5,-1792.68) -1541.16,-1771.34 v1(-1537.5,-1775)
  Bottom Layer w9: v1(-2825,-1662.5) R447P.1@-2750,-1662.5
D3A_N: C399C.2 R7C.1 R399C.1 U3C.6 U35A.4 | length 3892.7
  Top Layer w9: U3C.6@-2563.78,1662.5 v1(-2525,1662.5) -2475.59,1662.5 R7C.1@-2475,1663.09 ; v1(-1562.5,1737.5) ccw(c-1557.5,1737.5) -1557.5,1732.5 -1547.5,1732.5 cw(c-1547.5,1696.42) -1511.42,1696.42 U35A.4@-1511.42,1577.5
  Int6 (SB) w6: v1(-2525,1662.5) ccw(c-2585.36,1602.14) -2585.36,1687.5 -2650,1687.5 ccw(c-2650,1662.5) -2675,1662.5 ccw(c-2650,1662.5) -2650,1637.5 ; v1@-1562.86,1737.75 cw(c-1587.5,1755.18) -1587.5,1725 -1987.5,1725 ccw(c-1987.5,1694.82) -2008.84,1716.16 -2078.66,1646.34 cw(c-2100,1667.68) -2100,1637.5 ; -2650,1637.5 -2100,1637.5 ; -2650,1637.5 -2100,1637.5 ; -2650,1637.5 -2100,1637.5 ; -2650,1637.5 -2100,1637.5 ; -2650,1637.5 -2100,1637.5
  Bottom Layer w9: R399C.1@-2600,1662.5 v1(-2525,1662.5)
D3A_P: C463C.2 R8C.1 R447C.1 U3C.2 U35A.5 | length 2337.1
  Top Layer w9: U3C.2@-2786.22,1712.5 v1(-2825,1712.5) cw(c-2825,1737.5) -2850,1737.5 -2850,1762.5 cw(c-2812.5,1762.5) -2812.5,1800 -2511.91,1800 ; v1(-1562.5,1712.5) cw(c-1557.5,1712.5) -1557.5,1717.5 -1547.5,1717.5 cw(c-1547.5,1701.1) -1531.1,1701.1 U35A.5@-1531.1,1577.5 ; -2511.91,1800 cw(c-2511.91,1763.09) R8C.1@-2475,1763.09 ; -2511.91,1800 cw(c-2511.91,1763.09) R8C.1@-2475,1763.09 ; -2511.91,1800 cw(c-2511.91,1763.09) R8C.1@-2475,1763.09 ; -2511.91,1800 cw(c-2511.91,1763.09) R8C.1@-2475,1763.09 ; -2511.91,1800 cw(c-2511.91,1763.09) R8C.1@-2475,1763.09
  Int5 (ST) w6: v1(-2825,1712.5) ccw(c-2800,1712.5) -2800,1687.5 -2700,1687.5 cw(c-2700,1662.5) -2675,1662.5 ccw(c-2650,1662.5) -2650,1637.5 -2100,1637.5 ccw(c-2100,1667.68) -2078.66,1646.34 -2008.84,1716.16 cw(c-1987.5,1694.82) -1987.5,1725 -1592.68,1725 ; v1(-1562.5,1712.5) ccw(c-1592.68,1682.32) -1592.5,1725 ; -1592.68,1725 cw(c-1592.68,1682.32) -1592.5,1725 ; -1592.68,1725 -1592.5,1725
  Bottom Layer w9: v1(-2825,1712.5) R447C.1@-2750,1712.5
D3B_N: C399G.2 R7G.1 R399G.1 U3G.6 U35B.4 | length 6642.7
  Top Layer w9: U3G.6@-2563.78,762.5 v1(-2525,762.5) -2475.59,762.5 R7G.1@-2475,763.09 ; v1(-1562.5,837.5) ccw(c-1557.5,837.5) -1557.5,832.5 -1547.5,832.5 cw(c-1547.5,796.42) -1511.42,796.42 U35B.4@-1511.42,677.5
  Int6 (SB) w6: v1(-2525,762.5) ccw(c-2585.36,702.14) -2585.36,787.5 -2650,787.5 ccw(c-2650,762.5) -2675,762.5 ccw(c-2650,762.5) -2650,737.5 ; v1@-1562.86,837.75 cw(c-1587.5,855.18) -1587.5,825 -1987.5,825 ccw(c-1987.5,794.82) -2008.84,816.16 -2078.66,746.34 cw(c-2100,767.68) -2100,737.5 ; -2650,737.5 -2100,737.5 ; -2650,737.5 -2100,737.5 ; -2650,737.5 -2100,737.5 ; -2650,737.5 -2100,737.5 ; -2650,737.5 -2100,737.5 ; -2650,737.5 -2100,737.5 ; -2650,737.5 -2100,737.5 ; -2650,737.5 -2100,737.5 ; -2650,737.5 -2100,737.5 ; -2650,737.5 -2100,737.5
  Bottom Layer w9: R399G.1@-2600,762.5 v1(-2525,762.5)
D3B_P: C463G.2 R8G.1 R447G.1 U3G.2 U35B.5 | length 2887.1
  Top Layer w9: U3G.2@-2786.22,812.5 v1(-2825,812.5) cw(c-2825,837.5) -2850,837.5 -2850,862.5 cw(c-2812.5,862.5) -2812.5,900 -2511.91,900 ; v1(-1562.5,812.5) cw(c-1557.5,812.5) -1557.5,817.5 -1547.5,817.5 cw(c-1547.5,801.1) -1531.1,801.1 U35B.5@-1531.1,677.5 ; -2511.91,900 cw(c-2511.91,863.09) R8G.1@-2475,863.09 ; -2511.91,900 cw(c-2511.91,863.09) R8G.1@-2475,863.09 ; -2511.91,900 cw(c-2511.91,863.09) R8G.1@-2475,863.09 ; -2511.91,900 cw(c-2511.91,863.09) R8G.1@-2475,863.09 ; -2511.91,900 cw(c-2511.91,863.09) R8G.1@-2475,863.09
  Int5 (ST) w6: v1(-2825,812.5) ccw(c-2800,812.5) -2800,787.5 -2700,787.5 cw(c-2700,762.5) -2675,762.5 ccw(c-2650,762.5) -2650,737.5 ; v1(-1562.5,812.5) ccw(c-1592.68,782.32) -1592.5,825 ; -2650,737.5 -2100,737.5 ; -2650,737.5 -2100,737.5 ; -2100,737.5 ccw(c-2100,767.68) -2078.66,746.34 -2008.84,816.16 cw(c-1987.5,794.82) -1987.5,825 -1592.68,825 ; -1592.68,825 cw(c-1592.68,782.32) -1592.5,825 ; -1592.68,825 -1592.5,825
  Bottom Layer w9: v1(-2825,812.5) R447G.1@-2750,812.5
D3C_N: C399K.2 R7K.1 R399K.1 U3K.6 U35C.4 | length 6642.7
  Top Layer w9: U3K.6@-2563.78,-137.5 v1(-2525,-137.5) -2475.59,-137.5 R7K.1@-2475,-136.91 ; v1(-1562.5,-62.5) ccw(c-1557.5,-62.5) -1557.5,-67.5 -1547.5,-67.5 cw(c-1547.5,-103.58) -1511.42,-103.58 U35C.4@-1511.42,-222.5
  Int6 (SB) w6: v1(-2525,-137.5) ccw(c-2585.36,-197.86) -2585.36,-112.5 -2650,-112.5 ccw(c-2650,-137.5) -2675,-137.5 ccw(c-2650,-137.5) -2650,-162.5 ; v1@-1562.86,-62.25 cw(c-1587.5,-44.82) -1587.5,-75 -1987.5,-75 ccw(c-1987.5,-105.18) -2008.84,-83.84 -2078.66,-153.66 cw(c-2100,-132.32) -2100,-162.5 ; -2650,-162.5 -2100,-162.5 ; -2650,-162.5 -2100,-162.5 ; -2650,-162.5 -2100,-162.5 ; -2650,-162.5 -2100,-162.5 ; -2650,-162.5 -2100,-162.5 ; -2650,-162.5 -2100,-162.5 ; -2650,-162.5 -2100,-162.5 ; -2650,-162.5 -2100,-162.5 ; -2650,-162.5 -2100,-162.5 ; -2650,-162.5 -2100,-162.5
  Bottom Layer w9: R399K.1@-2600,-137.5 v1(-2525,-137.5)
D3C_P: C463K.2 R8K.1 R447K.1 U3K.2 U35C.5 | length 2887.1
  Top Layer w9: U3K.2@-2786.22,-87.5 v1(-2825,-87.5) cw(c-2825,-62.5) -2850,-62.5 -2850,-37.5 cw(c-2812.5,-37.5) -2812.5,0 -2511.91,0 ; v1(-1562.5,-87.5) cw(c-1557.5,-87.5) -1557.5,-82.5 -1547.5,-82.5 cw(c-1547.5,-98.9) -1531.1,-98.9 U35C.5@-1531.1,-222.5 ; -2511.91,0 cw(c-2511.91,-36.91) R8K.1@-2475,-36.91 ; -2511.91,0 cw(c-2511.91,-36.91) R8K.1@-2475,-36.91 ; -2511.91,0 cw(c-2511.91,-36.91) R8K.1@-2475,-36.91 ; -2511.91,0 cw(c-2511.91,-36.91) R8K.1@-2475,-36.91 ; -2511.91,0 cw(c-2511.91,-36.91) R8K.1@-2475,-36.91
  Int5 (ST) w6: v1(-2825,-87.5) ccw(c-2800,-87.5) -2800,-112.5 -2700,-112.5 cw(c-2700,-137.5) -2675,-137.5 ccw(c-2650,-137.5) -2650,-162.5 ; v1(-1562.5,-87.5) ccw(c-1592.68,-117.68) -1592.5,-75 ; -2650,-162.5 -2100,-162.5 ; -2650,-162.5 -2100,-162.5 ; -2100,-162.5 ccw(c-2100,-132.32) -2078.66,-153.66 -2008.84,-83.84 cw(c-1987.5,-105.18) -1987.5,-75 -1592.68,-75 ; -1592.68,-75 cw(c-1592.68,-117.68) -1592.5,-75 ; -1592.68,-75 -1592.5,-75
  Bottom Layer w9: v1(-2825,-87.5) R447K.1@-2750,-87.5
